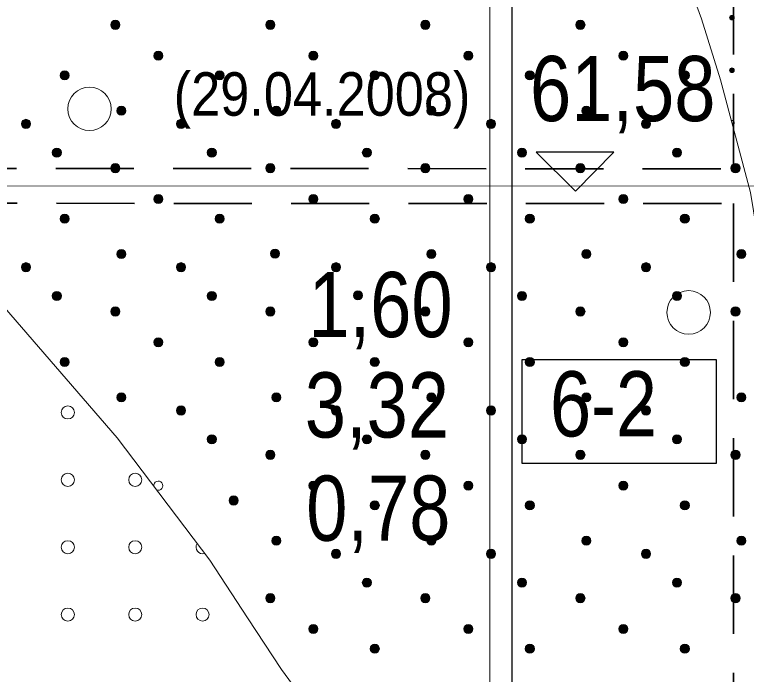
# Model space of a CAD drawing. Extents: x 640121 to 640955, y 6441885 to 6442246.
# Drawn here: x 640239.34 to 640273.01, y 6441932.04 to 6441962.4 of the extents above; entities that cross this region are included whole.
import ezdxf
from ezdxf.enums import TextEntityAlignment as Align

# ---------------------------------------------------------------- set-up
doc = ezdxf.new("R2010")
doc.units = 0
doc.header["$LTSCALE"] = 1.2
doc.linetypes.add('MEDIUM_DASHED', pattern=[4.5, 3, -1.5])
for name, color, linetype, lineweight in [('31', 7, 'Continuous', 13), ('32', 7, 'Continuous', 13), ('33', 7, 'Continuous', 13), ('34', 7, 'Continuous', 25), ('35', 7, 'Continuous', 35), ('43', 7, 'Continuous', 13), ('44', 7, 'Continuous', 13), ('45', 7, 'Continuous', 13), ('47', 7, 'Continuous', 13)]:
    doc.layers.add(name, color=color, linetype=linetype, lineweight=lineweight)

msp = doc.modelspace()

# ---------------------------------------------------------------- hatches: boundary and pattern name
at = {"layer": '44'}
for points in [[(640244.185, 6441961.932, 1), (640243.765, 6441961.932, 1)], [(640251.318, 6441961.932, 1), (640250.898, 6441961.932, 1)], [(640258.451, 6441961.932, 1), (640258.031, 6441961.932, 1)], [(640265.584, 6441961.932, 1), (640265.164, 6441961.932, 1)], [(640246.162, 6441960.513, 1), (640245.742, 6441960.513, 1)], [(640253.295, 6441960.513, 1), (640252.875, 6441960.513, 1)], [(640260.428, 6441960.513, 1), (640260.008, 6441960.513, 1)], [(640267.561, 6441960.513, 1), (640267.141, 6441960.513, 1)], [(640241.856, 6441959.605, 1), (640241.436, 6441959.605, 1)], [(640248.989, 6441959.605, 1), (640248.569, 6441959.605, 1)], [(640256.122, 6441959.605, 1), (640255.702, 6441959.605, 1)], [(640263.255, 6441959.605, 1), (640262.835, 6441959.605, 1)], [(640270.388, 6441959.605, 1), (640269.968, 6441959.605, 1)], [(640244.459, 6441957.98, 1), (640244.039, 6441957.98, 1)], [(640251.592, 6441957.98, 1), (640251.172, 6441957.98, 1)], [(640258.725, 6441957.98, 1), (640258.305, 6441957.98, 1)], [(640265.858, 6441957.98, 1), (640265.438, 6441957.98, 1)], [(640240.073, 6441957.374, 1), (640239.653, 6441957.374, 1)], [(640247.206, 6441957.374, 1), (640246.786, 6441957.374, 1)], [(640254.339, 6441957.374, 1), (640253.919, 6441957.374, 1)], [(640261.472, 6441957.374, 1), (640261.052, 6441957.374, 1)], [(640268.605, 6441957.374, 1), (640268.185, 6441957.374, 1)], [(640241.492, 6441956.052, 1), (640241.072, 6441956.052, 1)], [(640248.625, 6441956.052, 1), (640248.205, 6441956.052, 1)], [(640255.758, 6441956.052, 1), (640255.338, 6441956.052, 1)], [(640262.891, 6441956.052, 1), (640262.471, 6441956.052, 1)], [(640270.024, 6441956.052, 1), (640269.604, 6441956.052, 1)], [(640244.185, 6441955.336, 1), (640243.765, 6441955.336, 1)], [(640251.318, 6441955.336, 1), (640250.898, 6441955.336, 1)], [(640258.451, 6441955.336, 1), (640258.031, 6441955.336, 1)], [(640265.584, 6441955.336, 1), (640265.164, 6441955.336, 1)], [(640272.717, 6441955.336, 1), (640272.297, 6441955.336, 1)], [(640246.162, 6441953.917, 1), (640245.742, 6441953.917, 1)], [(640253.295, 6441953.917, 1), (640252.875, 6441953.917, 1)], [(640260.428, 6441953.917, 1), (640260.008, 6441953.917, 1)], [(640267.561, 6441953.917, 1), (640267.141, 6441953.917, 1)], [(640241.856, 6441953.009, 1), (640241.436, 6441953.009, 1)], [(640248.989, 6441953.009, 1), (640248.569, 6441953.009, 1)], [(640256.122, 6441953.009, 1), (640255.702, 6441953.009, 1)], [(640263.255, 6441953.009, 1), (640262.835, 6441953.009, 1)], [(640270.388, 6441953.009, 1), (640269.968, 6441953.009, 1)], [(640244.459, 6441951.384, 1), (640244.039, 6441951.384, 1)], [(640251.531, 6441951.402, 1), (640251.111, 6441951.402, 1)], [(640258.725, 6441951.384, 1), (640258.305, 6441951.384, 1)], [(640265.858, 6441951.384, 1), (640265.438, 6441951.384, 1)], [(640272.991, 6441951.384, 1), (640272.571, 6441951.384, 1)], [(640240.073, 6441950.778, 1), (640239.653, 6441950.778, 1)], [(640247.206, 6441950.778, 1), (640246.786, 6441950.778, 1)], [(640254.339, 6441950.778, 1), (640253.919, 6441950.778, 1)], [(640261.472, 6441950.778, 1), (640261.052, 6441950.778, 1)], [(640268.605, 6441950.778, 1), (640268.185, 6441950.778, 1)], [(640241.492, 6441949.456, 1), (640241.072, 6441949.456, 1)], [(640248.625, 6441949.456, 1), (640248.205, 6441949.456, 1)], [(640255.347, 6441949.482, 1), (640254.927, 6441949.482, 1)], [(640262.891, 6441949.456, 1), (640262.471, 6441949.456, 1)], [(640270.024, 6441949.456, 1), (640269.604, 6441949.456, 1)], [(640244.185, 6441948.74, 1), (640243.765, 6441948.74, 1)], [(640251.318, 6441948.74, 1), (640250.898, 6441948.74, 1)], [(640258.451, 6441948.74, 1), (640258.031, 6441948.74, 1)], [(640265.584, 6441948.74, 1), (640265.164, 6441948.74, 1)], [(640272.717, 6441948.74, 1), (640272.297, 6441948.74, 1)], [(640246.162, 6441947.321, 1), (640245.742, 6441947.321, 1)], [(640253.295, 6441947.321, 1), (640252.875, 6441947.321, 1)], [(640260.428, 6441947.321, 1), (640260.008, 6441947.321, 1)], [(640267.561, 6441947.321, 1), (640267.141, 6441947.321, 1)], [(640241.856, 6441946.413, 1), (640241.436, 6441946.413, 1)], [(640248.989, 6441946.413, 1), (640248.569, 6441946.413, 1)], [(640256.122, 6441946.413, 1), (640255.702, 6441946.413, 1)], [(640263.255, 6441946.413, 1), (640262.835, 6441946.413, 1)], [(640270.388, 6441946.413, 1), (640269.968, 6441946.413, 1)], [(640244.459, 6441944.788, 1), (640244.039, 6441944.788, 1)], [(640251.592, 6441944.788, 1), (640251.172, 6441944.788, 1)], [(640258.725, 6441944.788, 1), (640258.305, 6441944.788, 1)], [(640265.858, 6441944.788, 1), (640265.438, 6441944.788, 1)], [(640272.991, 6441944.788, 1), (640272.571, 6441944.788, 1)], [(640247.206, 6441944.182, 1), (640246.786, 6441944.182, 1)], [(640254.339, 6441944.182, 1), (640253.919, 6441944.182, 1)], [(640261.472, 6441944.182, 1), (640261.052, 6441944.182, 1)], [(640268.605, 6441944.182, 1), (640268.185, 6441944.182, 1)], [(640248.625, 6441942.86, 1), (640248.205, 6441942.86, 1)], [(640255.758, 6441942.86, 1), (640255.338, 6441942.86, 1)], [(640262.891, 6441942.86, 1), (640262.471, 6441942.86, 1)], [(640270.024, 6441942.86, 1), (640269.604, 6441942.86, 1)], [(640251.318, 6441942.144, 1), (640250.898, 6441942.144, 1)], [(640258.451, 6441942.144, 1), (640258.031, 6441942.144, 1)], [(640265.584, 6441942.144, 1), (640265.164, 6441942.144, 1)], [(640272.717, 6441942.144, 1), (640272.297, 6441942.144, 1)], [(640253.295, 6441940.725, 1), (640252.875, 6441940.725, 1)], [(640260.428, 6441940.725, 1), (640260.008, 6441940.725, 1)], [(640267.561, 6441940.725, 1), (640267.141, 6441940.725, 1)], [(640249.631, 6441940.042, 1), (640249.211, 6441940.042, 1)], [(640256.122, 6441939.817, 1), (640255.702, 6441939.817, 1)], [(640263.255, 6441939.817, 1), (640262.835, 6441939.817, 1)], [(640270.388, 6441939.817, 1), (640269.968, 6441939.817, 1)], [(640251.592, 6441938.192, 1), (640251.172, 6441938.192, 1)], [(640258.725, 6441938.192, 1), (640258.305, 6441938.192, 1)], [(640265.858, 6441938.192, 1), (640265.438, 6441938.192, 1)], [(640272.991, 6441938.192, 1), (640272.571, 6441938.192, 1)], [(640254.339, 6441937.586, 1), (640253.919, 6441937.586, 1)], [(640261.472, 6441937.586, 1), (640261.052, 6441937.586, 1)], [(640268.605, 6441937.586, 1), (640268.185, 6441937.586, 1)], [(640255.758, 6441936.264, 1), (640255.338, 6441936.264, 1)], [(640262.891, 6441936.264, 1), (640262.471, 6441936.264, 1)], [(640270.024, 6441936.264, 1), (640269.604, 6441936.264, 1)], [(640251.318, 6441935.548, 1), (640250.898, 6441935.548, 1)], [(640258.451, 6441935.548, 1), (640258.031, 6441935.548, 1)], [(640265.584, 6441935.548, 1), (640265.164, 6441935.548, 1)], [(640272.717, 6441935.548, 1), (640272.297, 6441935.548, 1)], [(640253.295, 6441934.129, 1), (640252.875, 6441934.129, 1)], [(640260.428, 6441934.129, 1), (640260.008, 6441934.129, 1)], [(640267.561, 6441934.129, 1), (640267.141, 6441934.129, 1)], [(640256.122, 6441933.221, 1), (640255.702, 6441933.221, 1)], [(640263.255, 6441933.221, 1), (640262.835, 6441933.221, 1)], [(640270.388, 6441933.221, 1), (640269.968, 6441933.221, 1)]]:
    msp.add_hatch(color=256, dxfattribs=at).paths.add_polyline_path(points)
at = {"layer": '45'}
for points in [[(640272.419, 6441962.335, 1), (640272.271, 6441962.186, 1)], [(640272.419, 6441959.917, 1), (640272.271, 6441959.768, 1)]]:
    msp.add_hatch(color=256, dxfattribs=at).paths.add_polyline_path(points)

# ---------------------------------------------------------------- linework, layer by layer
at = {"layer": '31'}
for points in [[(640279.06, 6441928.41), (640278.87, 6441928.63), (640278.5, 6441929.22), (640278.1, 6441930.16), (640277.77, 6441931.22), (640277.06, 6441933.92), (640275.96, 6441939.13), (640274.35, 6441947.19), (640273.2, 6441954.22), (640271.82, 6441959.4), (640270.94, 6441962.21), (640269.15, 6441967.1), (640267.95, 6441969.83), (640266.26, 6441973.93), (640264.74, 6441977.03), (640263.9, 6441978.29), (640263.08, 6441979.24)], [(640219.5, 6441962.07), (640223.33, 6441960.67), (640227.82, 6441958.13), (640230.7, 6441955.94), (640234.62, 6441952.84), (640238.88, 6441948.92), (640244.06, 6441942.93), (640248.32, 6441937.29), (640250.05, 6441934.64), (640251.62, 6441932.26), (640252.58, 6441930.95), (640255.23, 6441927.27), (640257.4, 6441925.27)]]:
    msp.add_lwpolyline(points, dxfattribs=at)
at = {"layer": '32', "lineweight": 25}
msp.add_line((640262.21, 6441981.41), (640262.21, 6441921.41), dxfattribs=at)
at = {"layer": '33'}
msp.add_lwpolyline([(640261.21, 6441967.4), (640261.21, 6441926.41), (640262.19, 6441926.41), (640262.19, 6441926.41), (640262.21, 6441926.41), (640262.21, 6441967.41), (640261.72, 6441967.41)], close=True, dxfattribs=at)
at = {"layer": '33', "lineweight": 25}
msp.add_lwpolyline([(640262.7, 6441946.53), (640271.62, 6441946.53), (640271.62, 6441941.75), (640262.7, 6441941.75)], close=True, dxfattribs=at)
at = {"layer": '34', "lineweight": 13}
msp.add_lwpolyline([(640160.01, 6441951.16), (640175.15, 6441951.4), (640211.9, 6441953.4), (640235.85, 6441954.52), (640281.21, 6441954.51), (640334.24, 6441954.41), (640399.04, 6441956.94), (640444.67, 6441958.31), (640465.01, 6441958.56)], dxfattribs=at)
at = {"layer": '34'}
msp.add_lwpolyline([(640263.34, 6441956.08), (640265.14, 6441954.27), (640266.91, 6441956.08)], close=True, dxfattribs=at)
at = {"layer": '35', "linetype": 'MEDIUM_DASHED'}
for p, q in [((640272.41, 6441974.96), (640272.41, 6441955.31)), ((640272.41, 6441953.71), (640272.41, 6441929.89))]:
    msp.add_line(p, q, dxfattribs=at)
for points in [[(640176.61, 6441952.28), (640211.86, 6441954.2), (640235.83, 6441955.32), (640272.41, 6441955.31)], [(640176.61, 6441950.68), (640211.95, 6441952.61), (640235.86, 6441953.72), (640272.41, 6441953.71)]]:
    msp.add_lwpolyline(points, dxfattribs=at)
at = {"layer": '43'}
for centre in [(640241.788, 6441944.093), (640241.788, 6441940.993), (640244.888, 6441940.993), (640241.788, 6441937.893), (640244.888, 6441937.893), (640241.788, 6441934.793), (640244.888, 6441934.793), (640247.988, 6441934.793)]:
    msp.add_circle(centre, 0.3, dxfattribs=at)
msp.add_arc((640247.988, 6441937.893), 0.3, 146.357, 287.7561, dxfattribs=at)
at = {"layer": '44'}
for centre in [(640243.975, 6441961.932), (640251.108, 6441961.932), (640258.241, 6441961.932), (640265.374, 6441961.932), (640245.952, 6441960.513), (640253.085, 6441960.513), (640260.218, 6441960.513), (640267.351, 6441960.513), (640241.646, 6441959.605), (640248.779, 6441959.605), (640255.912, 6441959.605), (640263.045, 6441959.605), (640270.178, 6441959.605), (640244.249, 6441957.98), (640251.382, 6441957.98), (640258.515, 6441957.98), (640265.648, 6441957.98), (640239.863, 6441957.374), (640246.996, 6441957.374), (640254.129, 6441957.374), (640261.262, 6441957.374), (640268.395, 6441957.374), (640241.282, 6441956.052), (640248.415, 6441956.052), (640255.548, 6441956.052), (640262.681, 6441956.052), (640269.814, 6441956.052), (640243.975, 6441955.336), (640251.108, 6441955.336), (640258.241, 6441955.336), (640265.374, 6441955.336), (640272.507, 6441955.336), (640245.952, 6441953.917), (640253.085, 6441953.917), (640260.218, 6441953.917), (640267.351, 6441953.917), (640241.646, 6441953.009), (640248.779, 6441953.009), (640255.912, 6441953.009), (640263.045, 6441953.009), (640270.178, 6441953.009), (640244.249, 6441951.384), (640251.321, 6441951.402), (640258.515, 6441951.384), (640265.648, 6441951.384), (640272.781, 6441951.384), (640239.863, 6441950.778), (640246.996, 6441950.778), (640254.129, 6441950.778), (640261.262, 6441950.778), (640268.395, 6441950.778), (640241.282, 6441949.456), (640248.415, 6441949.456), (640255.137, 6441949.482), (640262.681, 6441949.456), (640269.814, 6441949.456), (640243.975, 6441948.74), (640251.108, 6441948.74), (640258.241, 6441948.74), (640265.374, 6441948.74), (640272.507, 6441948.74), (640245.952, 6441947.321), (640253.085, 6441947.321), (640260.218, 6441947.321), (640267.351, 6441947.321), (640241.646, 6441946.413), (640248.779, 6441946.413), (640255.912, 6441946.413), (640263.045, 6441946.413), (640270.178, 6441946.413), (640244.249, 6441944.788), (640251.382, 6441944.788), (640258.515, 6441944.788), (640265.648, 6441944.788), (640272.781, 6441944.788), (640246.996, 6441944.182), (640254.129, 6441944.182), (640261.262, 6441944.182), (640268.395, 6441944.182), (640248.415, 6441942.86), (640255.548, 6441942.86), (640262.681, 6441942.86), (640269.814, 6441942.86), (640251.108, 6441942.144), (640258.241, 6441942.144), (640265.374, 6441942.144), (640272.507, 6441942.144), (640253.085, 6441940.725), (640260.218, 6441940.725), (640267.351, 6441940.725), (640249.421, 6441940.042), (640255.912, 6441939.817), (640263.045, 6441939.817), (640270.178, 6441939.817), (640251.382, 6441938.192), (640258.515, 6441938.192), (640265.648, 6441938.192), (640272.781, 6441938.192), (640254.129, 6441937.586), (640261.262, 6441937.586), (640268.395, 6441937.586), (640255.548, 6441936.264), (640262.681, 6441936.264), (640269.814, 6441936.264), (640251.108, 6441935.548), (640258.241, 6441935.548), (640265.374, 6441935.548), (640272.507, 6441935.548), (640253.085, 6441934.129), (640260.218, 6441934.129), (640267.351, 6441934.129), (640255.912, 6441933.221), (640263.045, 6441933.221), (640270.178, 6441933.221)]:
    msp.add_circle(centre, 0.21, dxfattribs=at)
msp.add_arc((640245.952, 6441940.725), 0.21, 247.3775, 186.7355, dxfattribs=at)
at = {"layer": '45'}
for centre in [(640272.345, 6441962.261), (640272.345, 6441959.842)]:
    msp.add_circle(centre, 0.105, dxfattribs=at)
msp.add_arc((640272.345, 6441957.424), 0.105, 284.8041, 105.0588, dxfattribs=at)
at = {"layer": '47'}
for centre in [(640242.786, 6441958.062), (640270.354, 6441948.699)]:
    msp.add_circle(centre, 1, dxfattribs=at)

# ---------------------------------------------------------------- texts
at = {"layer": '32', "width": 0.85}
for s, p in [('1,60', (640256.175, 6441947.56)), ('3,32', (640256.01, 6441942.94)), ('0,78', (640256.075, 6441938.19))]:
    msp.add_text(s, height=3, dxfattribs=at).set_placement(p, align=Align.CENTER)
at = {"layer": '33', "width": 0.85}
msp.add_text('6-2', height=3, dxfattribs=at).set_placement((640266.435, 6441942.99), align=Align.CENTER)
at = {"layer": '34'}
for s, height, width, p in [('61,58', 3, 0.85, (640267.32, 6441957.5)), ('(29.04.2008)', 2, 0.9, (640253.485, 6441957.75))]:
    msp.add_text(s, height=height, dxfattribs=dict(at, width=width)).set_placement(p, align=Align.CENTER)

doc.saveas('drawing.dxf')
